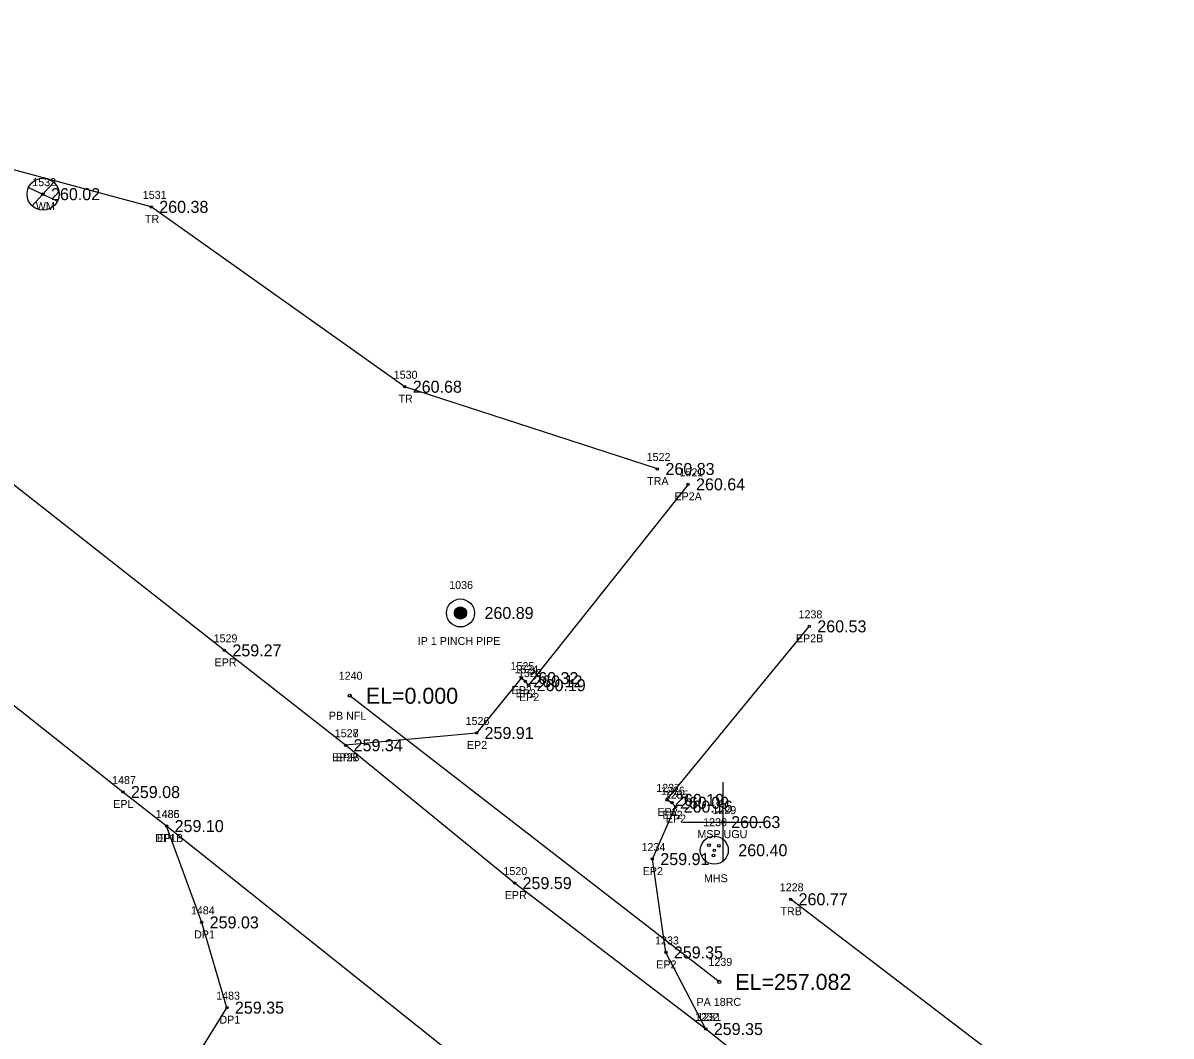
# Model space of a CAD drawing. Extents: x 1961231 to 1962574, y 799865 to 801120.
# Drawn here: x 1961710.5 to 1961853.9, y 800714.6 to 800841.2 of the extents above; entities that cross this region are included whole.
import ezdxf

# ---------------------------------------------------------------- set-up
doc = ezdxf.new("R2010")
doc.units = 0
for name, color, linetype in [('RD_EX_DR_Inlet', 7, 'Continuous'), ('RD_EX_DR_Pipe', 7, 'Continuous'), ('RD_EX_DR_Pipe_txCode', 7, 'Continuous'), ('RD_EX_Driveway', 7, 'Continuous'), ('RD_EX_Driveway_txCode', 7, 'Continuous'), ('RD_EX_DV_Prop_txCode', 7, 'Continuous'), ('RD_EX_DV_PropPin', 7, 'Continuous'), ('RD_EX_Misc', 7, 'Continuous'), ('RD_EX_Misc_txCode', 7, 'Continuous'), ('RD_EX_Road', 7, 'Continuous'), ('RD_EX_Road_txCode', 7, 'Continuous'), ('RD_EX_TX_Driveway_ELEV', 7, 'Continuous'), ('RD_EX_TX_DV_Prop_ELEV', 7, 'Continuous'), ('RD_EX_TX_Misc_ELEV', 7, 'Continuous'), ('RD_EX_TX_Road_ELEV', 7, 'Continuous'), ('RD_EX_TX_UT_ELEV', 7, 'Continuous'), ('RD_EX_TX_VEG_ELEV', 7, 'Continuous'), ('RD_EX_UT', 7, 'Continuous'), ('RD_EX_UT_txCode', 7, 'Continuous'), ('RD_EX_VEG', 7, 'Continuous'), ('RD_EX_VEG_txCode', 7, 'Continuous'), ('RD_SMD_Locator', 7, 'Continuous'), ('RD_TX_Pipe_ElevEX', 7, 'Continuous')]:
    doc.layers.add(name, color=color, linetype=linetype)

msp = doc.modelspace()

# ---------------------------------------------------------------- linework, layer by layer
at = {"layer": 'RD_EX_DR_Inlet'}
for centre, radius in [((1961796.83, 800737.84), 1.75), ((1961796.16, 800738.47), 0.175), ((1961797.39, 800738.4), 0.175), ((1961796.74, 800737.18), 0.175)]:
    msp.add_circle(centre, radius, dxfattribs=at)
at = {"layer": 'RD_EX_DR_Pipe'}
msp.add_line((1961797.45, 800721.38), (1961751.3, 800757.15), dxfattribs=at)
at = {"layer": 'RD_EX_Driveway'}
msp.add_lwpolyline([(1961801.42, 800682.57), (1961792.79, 800679.78), (1961785.2, 800682.11), (1961781.31, 800680.84), (1961776.43, 800674.97), (1961765.27, 800683.8), (1961771.82, 800693.99), (1961761.47, 800704.29), (1961751.75, 800711.21), (1961746.29, 800707.66), (1961742.29, 800702.88), (1961731.89, 800711.6), (1961735.94, 800718.16), (1961732.79, 800728.82), (1961728.41, 800740.86)], dxfattribs=at)
at = {"layer": 'RD_EX_DV_PropPin'}
for p, q in [((1961764.38, 800767.3), (1961764.38, 800767.69)), ((1961764.42, 800767.2), (1961764.42, 800767.79)), ((1961764.45, 800767.12), (1961764.45, 800767.86)), ((1961764.49, 800767.07), (1961764.49, 800767.92)), ((1961764.52, 800767.02), (1961764.52, 800767.97)), ((1961764.56, 800766.98), (1961764.56, 800768.01)), ((1961764.59, 800766.94), (1961764.59, 800768.05)), ((1961764.63, 800766.91), (1961764.63, 800768.08)), ((1961764.66, 800766.88), (1961764.66, 800768.1)), ((1961764.7, 800766.86), (1961764.7, 800768.13)), ((1961764.73, 800766.84), (1961764.73, 800768.15)), ((1961764.77, 800766.82), (1961764.77, 800768.17)), ((1961764.8, 800766.8), (1961764.8, 800768.19)), ((1961764.84, 800766.79), (1961764.84, 800768.2)), ((1961764.87, 800766.77), (1961764.87, 800768.21)), ((1961764.91, 800766.76), (1961764.91, 800768.23)), ((1961764.94, 800766.75), (1961764.94, 800768.24)), ((1961764.98, 800766.75), (1961764.98, 800768.24)), ((1961765.01, 800766.74), (1961765.01, 800768.25)), ((1961765.05, 800766.74), (1961765.05, 800768.25)), ((1961765.08, 800766.73), (1961765.08, 800768.25)), ((1961765.12, 800766.73), (1961765.12, 800768.26)), ((1961765.15, 800766.73), (1961765.15, 800768.25)), ((1961765.19, 800766.74), (1961765.19, 800768.25)), ((1961765.22, 800766.74), (1961765.22, 800768.25)), ((1961765.26, 800766.75), (1961765.26, 800768.24)), ((1961765.29, 800766.75), (1961765.29, 800768.24)), ((1961765.33, 800766.76), (1961765.33, 800768.23)), ((1961765.36, 800766.77), (1961765.36, 800768.21)), ((1961765.4, 800766.79), (1961765.4, 800768.2)), ((1961765.43, 800766.8), (1961765.43, 800768.19)), ((1961765.47, 800766.82), (1961765.47, 800768.17)), ((1961765.5, 800766.84), (1961765.5, 800768.15)), ((1961765.54, 800766.86), (1961765.54, 800768.13)), ((1961765.57, 800766.88), (1961765.57, 800768.1)), ((1961765.61, 800766.91), (1961765.61, 800768.08)), ((1961765.64, 800766.94), (1961765.64, 800768.05)), ((1961765.68, 800766.98), (1961765.68, 800768.01)), ((1961765.71, 800767.02), (1961765.71, 800767.97)), ((1961765.75, 800767.07), (1961765.75, 800767.92)), ((1961765.78, 800767.12), (1961765.78, 800767.86)), ((1961765.82, 800767.2), (1961765.82, 800767.79)), ((1961765.85, 800767.3), (1961765.85, 800767.69))]:
    msp.add_line(p, q, dxfattribs=at)
for radius in [1.75, 0.761]:
    msp.add_circle((1961765.12, 800767.49), radius, dxfattribs=at)
at = {"layer": 'RD_EX_Misc'}
for p, q in [((1961797.94, 800736.35), (1961797.94, 800746.35)), ((1961792.94, 800741.35), (1961802.94, 800741.35))]:
    msp.add_line(p, q, dxfattribs=at)
at = {"layer": 'RD_EX_Road'}
for points in [[(1962276.74, 800366.53), (1962275.76, 800367.28), (1962226.46, 800400.66), (1962183.05, 800429.73), (1962145.98, 800455.38), (1962104.4, 800484.06), (1962056.77, 800517.94), (1962023.95, 800541.05), (1961991.87, 800563.56), (1961983.89, 800569.94), (1961938.77, 800603.67), (1961913.43, 800623.83), (1961897.73, 800636.17), (1961851.62, 800671.61), (1961815.86, 800699.48), (1961795.77, 800715.49), (1961771.88, 800733.73), (1961750.77, 800750.96), (1961735.63, 800762.82), (1961702.92, 800788.52)], [(1961793.55, 800783.57), (1961773.63, 800758.47), (1961773.22, 800758.95), (1961772.71, 800759.35), (1961767.13, 800752.49), (1961750.77, 800750.96)], [(1962241.79, 800315.68), (1962238.35, 800317.6), (1962189.92, 800352.69), (1962151.64, 800383.49), (1962113.78, 800416.39), (1962074.11, 800451.29), (1962034.78, 800486.96), (1962017.07, 800503.17), (1961999.46, 800519.25), (1961962.48, 800552.12), (1961937.08, 800573.11), (1961923.19, 800584.9), (1961883.07, 800617.43), (1961838.29, 800653.43), (1961801.42, 800682.57), (1961728.41, 800740.86), (1961722.95, 800745.11), (1961689.13, 800771.93)], [(1961795.77, 800715.49), (1961790.78, 800725.06), (1961789.09, 800736.73), (1961791.99, 800743.29), (1961791.54, 800743.77), (1961790.92, 800744.13), (1961808.7, 800765.82)]]:
    msp.add_lwpolyline(points, dxfattribs=at)
at = {"layer": 'RD_EX_UT'}
for p, q in [((1961711.14, 800820.68), (1961714.77, 800818.97)), ((1961711.62, 800818.39), (1961714.29, 800821.28))]:
    msp.add_line(p, q, dxfattribs=at)
msp.add_circle((1961712.97, 800819.84), 2, dxfattribs=at)
at = {"layer": 'RD_EX_VEG'}
for points in [[(1961789.73, 800785.49), (1961758.16, 800795.77), (1961726.49, 800818.25), (1961689.15, 800828.3), (1961645.31, 800860.5), (1961608.13, 800895.26), (1961564.66, 800923.57), (1961511.61, 800961.39)], [(1961991.65, 800601.73), (1961952.54, 800620.78), (1961908.97, 800652.23), (1961862.96, 800688.46), (1961806.36, 800731.71)]]:
    msp.add_lwpolyline(points, dxfattribs=at)
at = {"layer": 'RD_SMD_Locator'}
for centre, radius in [((1961712.97, 800819.84), 0.15), ((1961726.49, 800818.25), 0.15), ((1961758.16, 800795.77), 0.15), ((1961789.73, 800785.49), 0.15), ((1961793.55, 800783.57), 0.15), ((1961765.12, 800767.49), 0.15), ((1961808.7, 800765.82), 0.15), ((1961735.63, 800762.82), 0.15), ((1961772.71, 800759.35), 0.15), ((1961773.22, 800758.95), 0.15), ((1961751.3, 800757.15), 0.2), ((1961773.63, 800758.47), 0.15), ((1961767.13, 800752.49), 0.15), ((1961750.77, 800750.96), 0.15), ((1961750.77, 800750.96), 0.15), ((1961722.95, 800745.11), 0.15), ((1961790.92, 800744.13), 0.15), ((1961791.54, 800743.77), 0.15), ((1961791.99, 800743.29), 0.15), ((1961797.94, 800741.35), 0.15), ((1961728.41, 800740.86), 0.15), ((1961728.41, 800740.86), 0.15), ((1961796.83, 800737.84), 0.15), ((1961789.09, 800736.73), 0.15), ((1961771.88, 800733.73), 0.15), ((1961806.36, 800731.71), 0.15), ((1961732.79, 800728.82), 0.15), ((1961790.78, 800725.06), 0.15), ((1961797.45, 800721.38), 0.2), ((1961735.94, 800718.16), 0.15), ((1961795.77, 800715.49), 0.15), ((1961795.77, 800715.49), 0.15)]:
    msp.add_circle(centre, radius, dxfattribs=at)

# ---------------------------------------------------------------- texts
at = {"layer": 'RD_EX_DR_Pipe_txCode'}
for s, p in [('1240', (1961749.91, 800759.15)), ('PB NFL', (1961748.68, 800754.15)), ('1239', (1961796.1, 800723.38)), ('PA 18RC', (1961794.61, 800718.38))]:
    msp.add_text(s, height=1, dxfattribs=at).set_placement(p)
at = {"layer": 'RD_EX_Driveway_txCode'}
for s, p in [('1485', (1961727.06, 800741.86)), ('DP1B', (1961726.99, 800738.86)), ('1484', (1961731.44, 800729.82)), ('DP1', (1961731.84, 800726.82)), ('1483', (1961734.6, 800719.16)), ('DP1', (1961735, 800716.16))]:
    msp.add_text(s, height=1, dxfattribs=at).set_placement(p)
at = {"layer": 'RD_EX_DV_Prop_txCode'}
for s, p in [('1036', (1961763.71, 800770.49)), ('IP 1 PINCH PIPE', (1961759.78, 800763.49))]:
    msp.add_text(s, height=1, dxfattribs=at).set_placement(p)
at = {"layer": 'RD_EX_Misc_txCode'}
for s, p in [('1229', (1961796.59, 800742.35)), ('MSP UGU', (1961794.72, 800739.35))]:
    msp.add_text(s, height=1, dxfattribs=at).set_placement(p)
at = {"layer": 'RD_EX_Road_txCode'}
for s, p in [('1521', (1961792.48, 800784.57)), ('EP2A', (1961791.85, 800781.57)), ('1238', (1961807.35, 800766.82)), ('1529', (1961734.28, 800763.82)), ('EP2B', (1961807.02, 800763.82)), ('EPR', (1961734.4, 800760.82)), ('1525', (1961771.37, 800760.35)), ('1524', (1961771.87, 800759.95)), ('1523', (1961772.29, 800759.47)), ('EP2', (1961771.51, 800757.35)), ('EP2', (1961772.01, 800756.95)), ('EP2', (1961772.43, 800756.47)), ('1526', (1961765.76, 800753.49)), ('1527', (1961749.42, 800751.96)), ('1528', (1961749.42, 800751.96)), ('EP2', (1961765.92, 800750.49)), ('EP2B', (1961749.09, 800748.96)), ('EPR', (1961749.54, 800748.96)), ('1487', (1961721.6, 800746.11)), ('1237', (1961789.58, 800745.13)), ('1236', (1961790.17, 800744.77)), ('1235', (1961790.64, 800744.29)), ('EPL', (1961721.74, 800743.11)), ('1486', (1961727.04, 800741.86)), ('EP2', (1961789.72, 800742.13)), ('EP2', (1961790.34, 800741.77)), ('EP2', (1961790.78, 800741.29)), ('EPL', (1961727.2, 800738.86)), ('1234', (1961787.74, 800737.73)), ('1520', (1961770.49, 800734.73)), ('EP2', (1961787.88, 800734.73)), ('EPR', (1961770.65, 800731.73)), ('1233', (1961789.43, 800726.06)), ('EP2', (1961789.58, 800723.06)), ('1232', (1961794.42, 800716.49)), ('1231', (1961794.71, 800716.49))]:
    msp.add_text(s, height=1, dxfattribs=at).set_placement(p)
at = {"layer": 'RD_EX_TX_Driveway_ELEV'}
for s, p in [('259.10', (1961729.41, 800740.11)), ('259.03', (1961733.79, 800728.07)), ('259.35', (1961736.94, 800717.41))]:
    msp.add_text(s, height=1.5, dxfattribs=at).set_placement(p)
at = {"layer": 'RD_EX_TX_DV_Prop_ELEV'}
msp.add_text('260.89', height=1.5, dxfattribs=at).set_placement((1961768.12, 800766.74))
at = {"layer": 'RD_EX_TX_Misc_ELEV'}
msp.add_text('260.63', height=1.5, dxfattribs=at).set_placement((1961798.94, 800740.6))
at = {"layer": 'RD_EX_TX_Road_ELEV'}
for s, p in [('260.64', (1961794.55, 800782.82)), ('260.53', (1961809.7, 800765.07)), ('259.27', (1961736.63, 800762.07)), ('260.32', (1961773.71, 800758.6)), ('260.12', (1961774.22, 800758.2)), ('260.19', (1961774.63, 800757.72)), ('259.91', (1961768.13, 800751.74)), ('259.34', (1961751.77, 800750.21)), ('259.34', (1961751.77, 800750.21)), ('259.08', (1961723.95, 800744.36)), ('260.19', (1961791.92, 800743.38)), ('260.09', (1961792.54, 800743.02)), ('260.16', (1961792.99, 800742.54)), ('259.10', (1961729.41, 800740.11)), ('259.91', (1961790.09, 800735.98)), ('259.59', (1961772.88, 800732.98)), ('259.35', (1961791.78, 800724.31)), ('259.35', (1961796.77, 800714.74)), ('259.35', (1961796.77, 800714.74))]:
    msp.add_text(s, height=1.5, dxfattribs=at).set_placement(p)
at = {"layer": 'RD_EX_TX_UT_ELEV'}
for s, p in [('260.02', (1961713.97, 800819.09)), ('260.40', (1961799.83, 800737.09))]:
    msp.add_text(s, height=1.5, dxfattribs=at).set_placement(p)
at = {"layer": 'RD_EX_TX_VEG_ELEV'}
for s, p in [('260.38', (1961727.49, 800817.5)), ('260.68', (1961759.16, 800795.02)), ('260.83', (1961790.73, 800784.74)), ('260.77', (1961807.36, 800730.96))]:
    msp.add_text(s, height=1.5, dxfattribs=at).set_placement(p)
at = {"layer": 'RD_EX_UT_txCode'}
for s, p in [('1532', (1961711.63, 800820.84)), ('WM', (1961712.07, 800817.84)), ('1230', (1961795.44, 800740.84)), ('MHS', (1961795.54, 800733.84))]:
    msp.add_text(s, height=1, dxfattribs=at).set_placement(p)
at = {"layer": 'RD_EX_VEG_txCode'}
for s, p in [('1531', (1961725.43, 800819.25)), ('TR', (1961725.7, 800816.25)), ('1530', (1961756.78, 800796.77)), ('TR', (1961757.37, 800793.77)), ('1522', (1961788.38, 800786.49)), ('TRA', (1961788.44, 800783.49)), ('1228', (1961805.01, 800732.71)), ('TRB', (1961805.09, 800729.71))]:
    msp.add_text(s, height=1, dxfattribs=at).set_placement(p)
at = {"layer": 'RD_TX_Pipe_ElevEX'}
for s, p in [('EL=0.000', (1961753.3, 800756.15)), ('EL=257.082', (1961799.45, 800720.38))]:
    msp.add_text(s, height=2, dxfattribs=at).set_placement(p)

doc.saveas('drawing.dxf')
